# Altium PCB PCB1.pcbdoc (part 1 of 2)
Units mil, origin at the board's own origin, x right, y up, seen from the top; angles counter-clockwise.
Board outline 4437 x 2665.4 mil, 2 copper layers (Top Layer, Bottom Layer), stack 62.206 mil thick; 104 components, 74 nets, 471 pads, 378 vias.
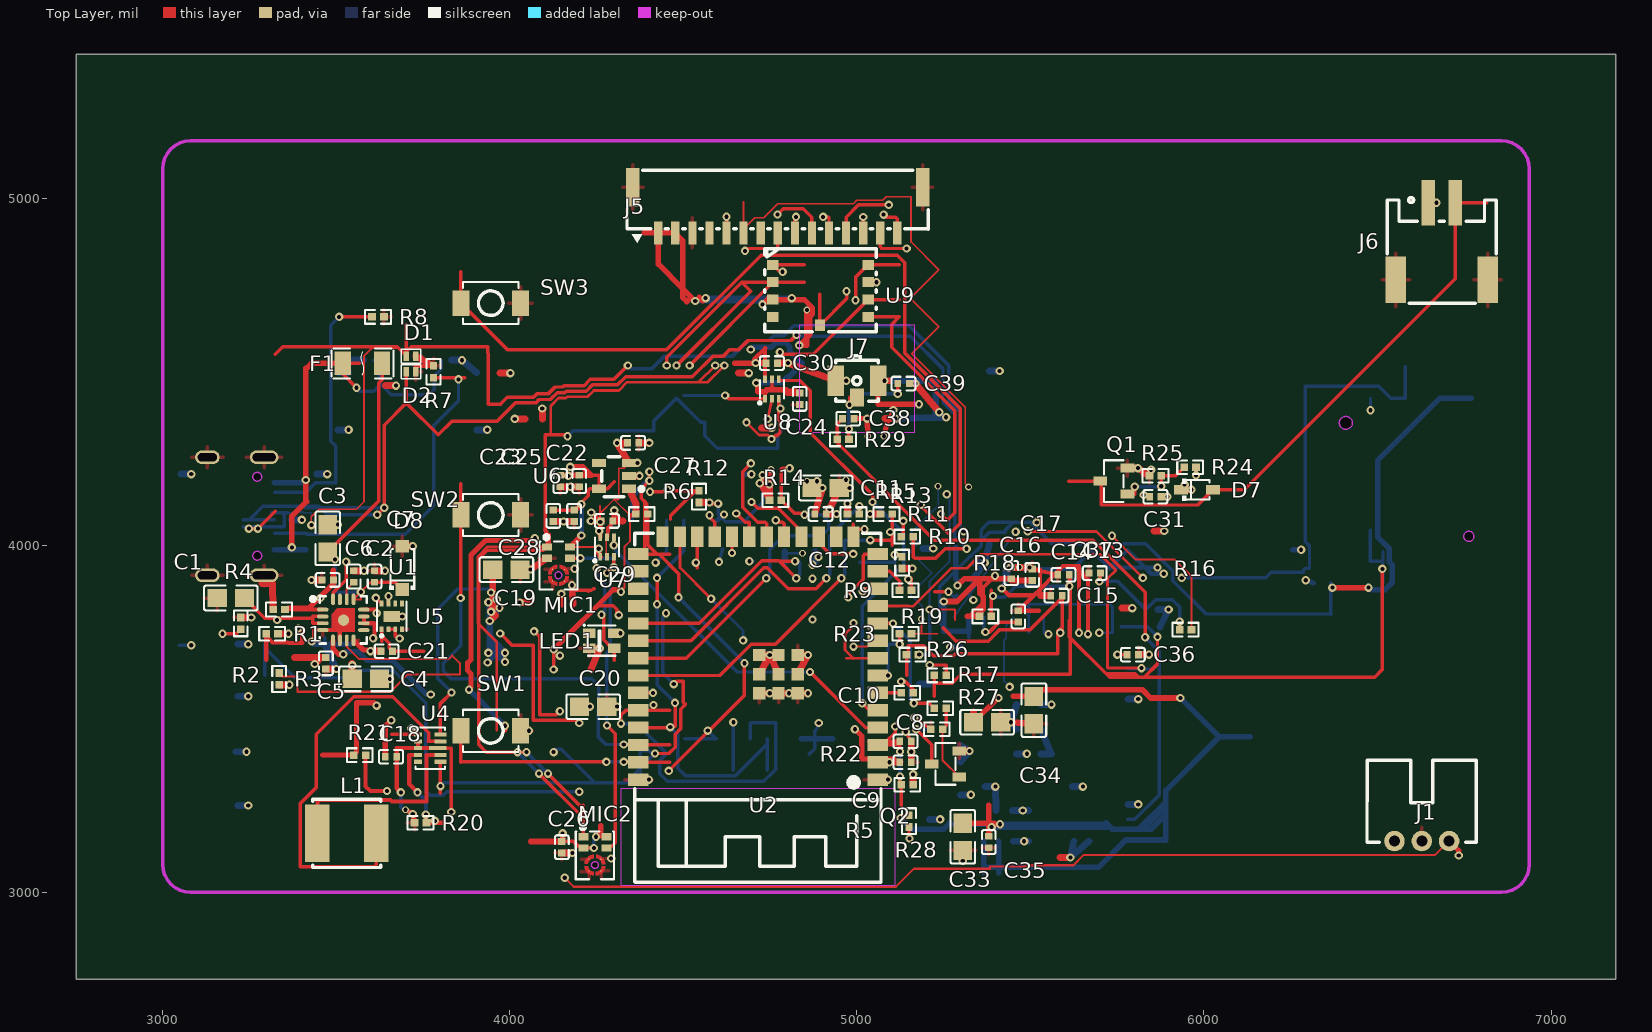
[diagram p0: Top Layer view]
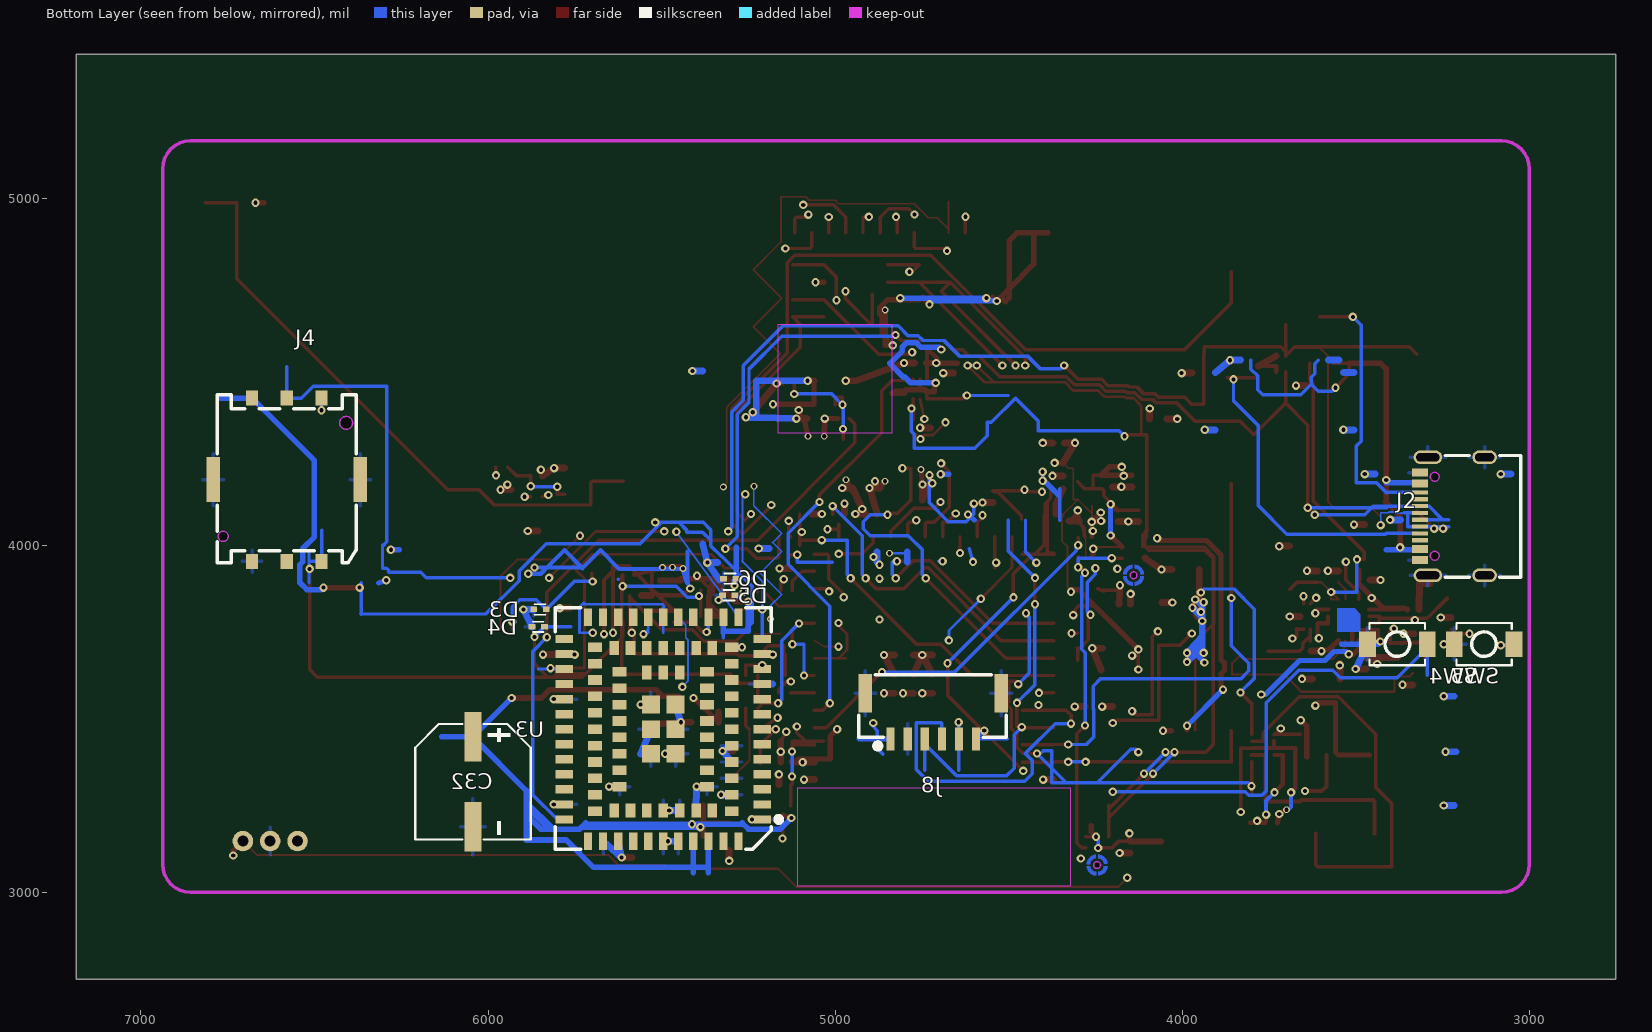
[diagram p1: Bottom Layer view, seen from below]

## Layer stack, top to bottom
Top Solder Mask Layer: solder mask 0.394, Dk 3.3
Top Layer: signal copper 1.379
Dielectric1: surface 59.449, FR4, Dk 4.5
Bottom Layer: signal copper 1.378
Bottom Solder Mask Layer: solder mask 0.394, Dk 3.3

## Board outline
7187,2750 2750,2750 2750,5415.4 7187,5415.4

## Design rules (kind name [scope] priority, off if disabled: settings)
BoardOutlineClearance copperThickness1oz [All] p0: genericclearance=10 ignorepadtopadclearanceinfootprint=FALSE except(0: Arc-SplitContinuation Track-SplitContinuation SMDPad-SplitContinuation THPad-SplitContinuation Via-SplitContinuation Fill-SplitContinuation Poly-SplitContinuation Region-SplitContinuation Text-SplitContinuation)
BoardOutlineClearance copperThickness2oz [All] p0: genericclearance=10 ignorepadtopadclearanceinfootprint=FALSE except(0: Arc-SplitContinuation Track-SplitContinuation SMDPad-SplitContinuation THPad-SplitContinuation Via-SplitContinuation Fill-SplitContinuation Poly-SplitContinuation Region-SplitContinuation Text-SplitContinuation)
BoardOutlineClearance otherClearance [All] p0: genericclearance=10 ignorepadtopadclearanceinfootprint=FALSE except(0: Arc-SplitContinuation Track-SplitContinuation SMDPad-SplitContinuation THPad-SplitContinuation Via-SplitContinuation Fill-SplitContinuation Poly-SplitContinuation Region-SplitContinuation Text-SplitContinuation)
Clearance copperThickness1oz [All] p1: gap=7 ignorepadtopadclearanceinfootprint=FALSE
Clearance copperThickness2oz [All] p1: gap=7 ignorepadtopadclearanceinfootprint=FALSE
Clearance otherClearance [All] p1: gap=7 ignorepadtopadclearanceinfootprint=FALSE
DiffPairsRouting differentialPair [All] p1: maxuncoupledlength=10 minlimit=6 maxlimit=Infinity mostfreqgap=6 toplayer_minwidth=5 toplayer_prefwidth=10 toplayer_maxwidth=100 bottomlayer_minwidth=5 bottomlayer_prefwidth=10 bottomlayer_maxwidth=100
PasteMaskExpansion pasteMaskExpansion [All] p1: expansion=0
PlaneConnect innerPlane [All] p1: planeconnectstyle=Relief reliefexpansion=20 reliefentries=4 reliefconductorwidth=10 reliefairgap=10
PolygonConnect copperRegion [All] p1: connectstyle=Relief reliefentries=4 reliefconductorwidth=10 polygonreliefangle="90 Angle" airgapwidth=10
RoutingVias viaSize [All] p1: viastyle="Through Hole" holewidth=12.0078 minholewidth=11.811 maxholewidth=248.0314 width=12.0078 minwidth=11.811 maxwidth=248.0314
SolderMaskExpansion solderMaskExpansion [IsVia] p1: useseparateexpansions=TRUE expansion=-1000 expansionbottom=-1000
SolderMaskExpansion solderMaskExpansion [All] p2: useseparateexpansions=TRUE expansion=2 expansionbottom=2
Width copperThickness1oz [All] p1: maxlimit=100 minlimit=5 preferedwidth=10
Width copperThickness2oz [All] p1: maxlimit=100 minlimit=8 preferedwidth=10

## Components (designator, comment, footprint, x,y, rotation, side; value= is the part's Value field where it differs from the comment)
C1 "10uF" C0805 3196.06,3848.03 r180 top
C2 "1uF" C0402 3610,3910 r90 top
C3 "10uF" C0805 3475,4020 r90 top
C4 "10uF" C0805 3585,3615 r0 top
C5 "100nF" C0402 3470,3660 r270 top
C6 "100nF" C0402 3550,3910 r90 top
C7 "100nF" C0402 3475,3900 r180 top
C8 "10uF" C0805 5375,3490 r0 top
C9 "100nF" C0402 5140,3375 r0 top
C10 "1uF" C0402 5140,3435 r0 top
C11 "10uF" C0805 4910,4165 r0 top
C12 "100nF" C0402 4895,4090 r0 top
C13 "33pF" C0402 5685,3920 r180 top
C14 "33pF" C0402 5595,3915 r180 top
C15 "33pF" C0402 5575,3855 r180 top
C16 "100nF" C0402 5445,3920 r90 top
C17 "33pF" C0402 5505,3915 r90 top
C18 "100nF" C0402 3657.5,3390.5 r0 top
C19 "10uF" C0805 3990,3930 r0 top
C20 "22uF" C0805 4240,3535 r0 top
C21 "100nF" C0402 3645,3695 r180 top
C22 "100nF" C0402 4145,4185 r270 top
C23 "100nF" C0402 4125,4085 r270 top
C24 "100nF" C0402 4835,4422 r270 top
C25 "100nF" C0402 4185,4085 r270 top
C26 "100nF" C0402 4150,3130 r270 top
C27 "1uF" C0402 4355,4295 r0 top
C28 "1uF" C0402 4200,4185 r270 top
C29 "100nF" C0402 4280,4070 r0 top
C30 "100nF" C0402 4755,4525 r0 top
C31 "100nF" C0402 5860,4140 r0 top
C32 "470uF" CAP-SMD_BD8.0-L8.3-W8.3-LS9.1-FD_RYRVE6.3V1000UF8X10 6043.31,3318.9 r270 bottom
C33 "22uF" C0805 5305,3160 r270 top
C34 "22uF" C0805 5510,3525 r270 top
C35 "100nF" C0402 5380,3145 r270 top
C36 "100nF" C0402 5795,3685 r0 top
C37 "10nF" C0402 5465,3795 r90 top
C38 "1pF" C0402 4975,4365 r0 top
C39 "1pF" C0402 5134,4466 r0 top
D1 "ESD5311N-2/TR" X1-DFN1006-2_L1.0-W0.6_ESD5311N-2-TR 3715,4545 r0 top locked
D2 "ESD5311N-2/TR" X1-DFN1006-2_L1.0-W0.6_ESD5311N-2-TR 3715,4500 r0 top locked
D3 "ESD9B5.0ST5G" SOD-923_L0.8-W0.6-LS1.0-BI 5850,3815 r0 bottom
D4 "ESD9B5.0ST5G" SOD-923_L0.8-W0.6-LS1.0-BI 5855,3765 r0 bottom
D5 "ESD9B5.0ST5G" SOD-923_L0.8-W0.6-LS1.0-BI 5306,3856 r0 bottom
D6 "ESD9B5.0ST5G" SOD-923_L0.8-W0.6-LS1.0-BI 5303,3904 r0 bottom
D7 "1N5819WS" SOD-323_L1.8-W1.3-LS2.5-RD 5980,4160 r0 top
D8 "SMF5.0A" SOD-123FL_L2.8-W1.7-LS3.6-RD 3690,3935 r90 top
F1 "1206L100/6NR" F1206 3575,4524 r0 top locked
J1 "PH-3AW" CONN-TH_3P-P2.00_DEALON_PH-3AW_C2904959 6627.54,3147.69 r180 top
J2 "TYPE-C16PIN" USB-C-SMD_TYPE-C16PIN 3221.5,4083.46 r90 bottom
J4 "NANO_SIM" SIM-SMD_XKB_XKNANO-1151 6579.72,4188.99 r0 bottom
J5 "BM15B-GHS-TBT" CONN-SMD_15P-P1.25_L5.0-W20.8 4771.85,4966 r180 top locked
J6 "XY-PH2.0-2PWT" CONN-SMD_XY-PH2.0-2PWT 6685.04,4875.73 r0 top
J7 "6GHz" RF-SMD_U.FL-R-SMT-1-80 5000,4450 r0 top locked
J8 "BM06B-GHS-TBT" CONN-SMD_6P-P1.25_BM06B-GHS-TBT 4716.93,3507.87 r0 bottom
L1 "1uH" IND-SMD_L5.0-W5.0_FNR50XXS 3530,3170 r180 top
LED1 "WS2812C-2020-V6/W" LED-SMD_4P-L2.0-W2.0-TL_WS2812B-2020 4265,3725 r0 top locked
MIC1 "MSM261DDB019" RHLGA-5L_L3.5-W2.7-P0.82-MSM261DDB019 4140,3945 r0 top locked
MIC2 "MSM261DDB019" RHLGA-5L_L3.5-W2.7-P0.82-MSM261DDB019 4245,3110 r0 top locked
Q1 "AO3400A" SOT-23-3_L2.9-W1.3-P1.90-LS2.4-BR 5740,4185 r0 top
Q2 "MMBT3904(RANGE:100-300)" SOT-23-3_L2.9-W1.3-P1.90-LS2.4-BR 5255,3370 r0 top
R1 "1.8kΩ" R0402 3315,3745 r0 top
R2 "1.1kΩ" R0402 3225,3775 r90 top
R3 "100kΩ" R0402 3335,3615 r270 top
R4 "10kΩ" R0402 3335,3815 r180 top
R5 "10kΩ" R0402 5145,3310 r0 top
R6 "10kΩ" R0402 4380,4090 r180 top
R7 "5.1kΩ" R0402 3780,4500 r90 top
R8 "5.1kΩ" R0402 3620,4658 r0 top
R9 "22Ω" R0402 5140,3870 r0 top
R10 "22Ω" R0402 5145,4025 r0 top
R11 "10kΩ" R0402 5085,4090 r180 top
R12 "10kΩ" R0402 4545,4140 r270 top
R13 "10kΩ" R0402 5130,3950 r270 top
R14 "10kΩ" R0402 4765,4130 r180 top
R15 "10kΩ" R0402 4990,4090 r180 top
R16 "22Ω" R0402 5946.85,3757.09 r180 top
R17 "22Ω" R0402 5240,3625 r180 top
R18 "10kΩ" R0402 5370,3795 r180 top
R19 "22Ω" R0402 5160,3685 r180 top
R20 "91kΩ" R0402 3742.5,3200.5 r180 top
R21 "511kΩ" R0402 3567.5,3395.5 r0 top
R22 "22Ω" R0402 5145,3575 r0 top
R23 "22Ω" R0402 5140,3745 r0 top
R24 "100Ω" R0402 5960,4225 r180 top
R25 "100kΩ" R0402 5860,4200 r180 top
R26 "4.7kΩ" R0402 5240,3530 r0 top
R27 "47kΩ" R0402 5230,3470 r180 top
R28 "0Ω" R0402 5150,3205 r90 top
R29 "0Ω" R0402 4960,4305 r0 top
SW1 "TS-1088-AR02016" SW-SMD_L3.9-W3.0-P4.45 3944.88,3465.35 r0 top
SW2 "TS-1088-AR02016" SW-SMD_L3.9-W3.0-P4.45 3944.88,4087.4 r0 top
SW3 "TS-1088-AR02016" SW-SMD_L3.9-W3.0-P4.45 3944.88,4697.64 r0 top
SW4 "TS-1088-AR02016" SW-SMD_L3.9-W3.0-P4.45 3380,3715 r0 bottom locked
SW5 "TS-1088-AR02016" SW-SMD_L3.9-W3.0-P4.45 3130,3715 r0 bottom locked
U1 "BQ24074RGTR" QFN-16_L3.0-W3.0-P0.50-TL-EP1.7 3520,3785 r0 top locked
U2 "2.4GHz" WIRELM-SMD_ESP32-S3-WROOM-1 4715,3675 r180 top locked
U3 "AIR780E" LGA-109_L17.7-W15.8-AIR780E 5495,3470 r0 bottom locked
U4 "TPS63802DLAR" VSON-10_L3.0-W2.0-P0.50-TL 3767.5,3415.5 r0 top
U5 "MAX17048G+T10" TDFN-8_L2.0-W2.0-P0.50-BL-EP1.2 3660,3795 r0 top locked
U6 "TLV75518PDBVR" SOT-23-5_L2.9-W1.6-P0.95-LS2.8-BR 4300,4200 r0 top locked
U7 "SN74AXC1T45DRLR" SOT-563_L1.6-W1.2-P0.50-LS1.6-BL 4280,3995 r0 top locked
U8 "SN74AXC1T45DRLR" SOT-563_L1.6-W1.2-P0.50-LS1.6-BL 4755,4450 r0 top locked
U9 "CSNP4GCR01-BPW" LGA-8_L8.0-W6.0-P1.27 4894.99,4720.83 r0 top

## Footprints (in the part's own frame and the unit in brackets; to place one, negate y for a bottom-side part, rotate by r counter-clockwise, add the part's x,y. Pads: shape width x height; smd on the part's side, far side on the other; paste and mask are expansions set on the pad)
C0402 [mm]
  rect 0.5x0.54 smd: 1(-0.42,0) 2(0.42,0)
  silkscreen extent -0.87,-0.5 0.87,0.5
C0805 [mm]
  rect 1.41x1.35 smd paste-100 mask+0.051: 1(-1,0) 2(1,0)
  silkscreen extent -1.96,-0.9 1.96,0.9
CAP-SMD_BD8.0-L8.3-W8.3-LS9.1-FD_RYRVE6.3V1000UF8X10 [mm]
  rect 3.61x1.26 smd: 1(-3.295,0) 2(3.295,0)
  silkscreen extent -4.23,-4.23 4.23,4.23
CONN-SMD_6P-P1.25_BM06B-GHS-TBT [mm]
  rect 0.6x1.7 smd: 1(3.125,1.675) 2(1.875,1.675) 3(0.625,1.675) 4(-0.625,1.675) 5(-1.875,1.675) 6(-3.125,1.675)
  rect 1x2.8 smd: 7(-4.975,-1.675) 8(4.975,-1.675)
  silkscreen extent -5.33,-3.02 5.46,2.59
CONN-SMD_15P-P1.25_L5.0-W20.8 [mm]
  rect 0.6x1.7 smd: 1(8.749,1.675) 2(7.499,1.675) 3(6.248,1.675) 4(4.998,1.675) 5(3.749,1.675) 6(2.499,1.675) 7(1.248,1.675) 8(-0.001,1.675) 9(-1.251,1.675) 10(-2.501,1.675) 11(-3.752,1.675) 12(-5.001,1.675) 13(-6.251,1.675) 14(-7.502,1.675) 15(-8.752,1.675)
  rect 1x2.8 smd: 16(-10.6,-1.675) 17(10.6,-1.675)
  silkscreen extent -11.02,-2.9 11.03,2.41
CONN-SMD_XY-PH2.0-2PWT [mm]
  rect 1x3.3 smd: 1(-1,2.825) 2(1,2.825)
  rect 1.5x3.4 smd: 3(3.35,-2.825) 4(-3.35,-2.825)
  silkscreen extent -3.98,-4.53 3.97,3.2
CONN-TH_3P-P2.00_DEALON_PH-3AW_C2904959 [mm]
  round 1.5 hole 0.8: 1(2,0) 2(0,0) 3(-2,0)
  silkscreen extent -4,-5.9 4.01,0.1
F1206 [mm]
  rect 1.19x1.728 smd: 1(-1.445,0) 2(1.445,0)
  silkscreen extent -2.27,-1.09 2.27,1.09
IND-SMD_L5.0-W5.0_FNR50XXS [mm]
  rect 1.8x4.2 smd: 1(-2.15,0) 2(2.15,0)
  silkscreen extent -2.5,-2.5 2.5,2.5
LED-SMD_4P-L2.0-W2.0-TL_WS2812B-2020 [mm]
  rect 0.9x0.7 smd: 1(-0.915,0.55) 2(-0.915,-0.55) 3(0.915,-0.55) 4(0.915,0.55)
  silkscreen extent -1.3,-1.1 1,1.15
LGA-8_L8.0-W6.0-P1.27 [mm]
  rect 0.74x0.85 smd paste+0 mask+0.05: 1(-0.047,-2.215)
  rect 0.85x0.74 smd paste+0 mask+0.05: 2(3.49,-1.595) 3(3.49,-0.325) 4(3.49,0.945) 5(3.49,2.215) 6(-3.49,2.215) 7(-3.49,0.945) 8(-3.49,-0.325) 9(-3.49,-1.595)
  silkscreen extent -4.06,-2.69 4.06,3.41
LGA-109_L17.7-W15.8-AIR780E [mm]
  rect 1.3x0.6 smd paste+0 mask+0.05: 1(-7.25,6.6) 2(-7.25,5.5) 3(-7.25,4.4) 4(-7.25,3.3) 5(-7.25,2.2) 6(-7.25,1.1) 7(-7.25,0) 8(-7.25,-1.1) 9(-7.25,-2.2) 10(-7.25,-3.3) 11(-7.25,-4.4) 12(-7.25,-5.5) 13(-7.25,-6.6) 23(7.25,-6.6) 24(7.25,-5.5) 25(7.25,-4.4) 26(7.25,-3.3) 27(7.25,-2.2) 28(7.25,-1.1) 29(7.25,0) 30(7.25,1.1) 31(7.25,2.2) 32(7.25,3.3) 33(7.25,4.4) 34(7.25,5.5) 35(7.25,6.6)
  rect 0.6x1.3 smd paste+0 mask+0.05: 14(-4.4,-8.2) 15(-3.3,-8.2) 16(-2.2,-8.2) 17(-1.1,-8.2) 18(0,-8.2) 19(1.1,-8.2) 20(2.2,-8.2) 21(3.3,-8.2) 22(4.4,-8.2) 36(4.4,8.2) 37(3.3,8.2) 38(2.2,8.2) 39(1.1,8.2) 40(0,8.2) 41(-1.1,8.2) 42(-2.2,8.2) 43(-3.3,8.2) 44(-4.4,8.2) 95(-5.5,-8.2) 96(5.5,-8.2) 97(5.5,8.2) 98(-5.5,8.2)
  rect 1x0.7 smd paste+0 mask+0.05: 45(-5,4.8) 46(-5,3.6) 47(-5,2.4) 48(-5,1.2) 49(-5,0) 50(-5,-1.2) 51(-5,-2.4) 52(-5,-3.6) 53(-5,-4.8) 59(5,-4.8) 60(5,-3.6) 61(5,-2.4) 62(5,-1.2) 63(5,0) 64(5,1.2) 65(5,2.4) 66(5,3.6) 67(5,4.8) 73(-3.2,4.2) 74(-3.2,3) 75(-3.2,1.8) 76(-3.2,0.6) 77(-3.2,-0.6) 78(-3.2,-1.8) 79(-3.2,-3) 80(-3.2,-4.2) 81(3.2,-4.2) 82(3.2,-3) 83(3.2,-1.8) 84(3.2,-0.6) 85(3.2,0.6) 86(3.2,1.8) 87(3.2,3) 88(3.2,4.2) 99(-5,6) 100(-5,-6) 103(5,-6) 104(5,6)
  rect 0.7x1 smd paste+0 mask+0.05: 54(-2.4,-5.95) 55(-1.2,-5.95) 56(0,-5.95) 57(1.2,-5.95) 58(2.4,-5.95) 68(2.4,5.95) 69(1.2,5.95) 70(0,5.95) 71(-1.2,5.95) 72(-2.4,5.95) 101(-3.6,-5.95) 102(3.6,-5.95) 105(3.6,5.95) 106(-3.6,5.95) 107(-1.2,-4.15) 108(0,-4.15) 109(1.2,-4.15)
  rect 1.3x1.3 smd paste+0 mask+0.05: 89(-0.9,1.8) 90(-0.9,0) 91(-0.9,-1.8) 92(0.9,-1.8) 93(0.9,0) 94(0.9,1.8)
  silkscreen extent -8.65,-8.9 7.9,8.8
QFN-16_L3.0-W3.0-P0.50-TL-EP1.7 [mm]
  oval 0.85x0.28 smd paste-100 mask+0.05: 1(-1.5,0.75) 2(-1.5,0.25) 3(-1.5,-0.25) 4(-1.5,-0.75) 9(1.5,-0.75) 10(1.5,-0.25) 11(1.5,0.25) 12(1.5,0.75)
  oval 0.28x0.85 smd paste-100 mask+0.05: 5(-0.75,-1.5) 6(-0.25,-1.5) 7(0.25,-1.5) 8(0.75,-1.5) 13(0.75,1.5) 14(0.25,1.5) 15(-0.25,1.5) 16(-0.75,1.5)
  round 0.827 smd: 17(0.023,-0.023)
  Top Layer region: 0.85,0.85 0.85,-0.85 -0.85,-0.85 -0.85,0.425 -0.425,0.85
  Bottom Layer region: 0.85,0.85 0.85,-0.85 -0.85,-0.85 -0.85,0.425 -0.425,0.85
  Multi-Layer region: 0.85,0.85 0.85,-0.85 -0.85,-0.85 -0.85,0.425 -0.425,0.85
  silkscreen extent -2.38,-1.72 1.72,1.73
R0402 [mm]
  rect 0.566x0.54 smd paste-100 mask+0.051: 1(-0.433,0) 2(0.433,0)
  silkscreen extent -0.94,-0.5 0.94,0.5
RF-SMD_U.FL-R-SMT-1-80 [mm]
  rect 1.2x2.2 smd: 1(-1.55,0.612) 3(1.55,0.612)
  rect 1x1.3 smd: 2(0,-0.612)
  silkscreen extent -1.55,-0.89 1.55,2.43
RHLGA-5L_L3.5-W2.7-P0.82-MSM261DDB019 [mm]
  rect 0.73x0.53 smd paste+0 mask+0.05: 1(-0.838,1.276) 2(-0.838,0.455) 4(0.838,0.455) 5(0.838,1.276)
  round 0.086 smd: 3(-0.437,-1.224) 3(-0.426,-0.36) 3(0.426,-1.235) 3(0.437,-0.371)
  Top Layer region: 0.085,-0.29 0.084,-0.039 0.144,-0.045 0.202,-0.055 0.265,-0.072 0.335,-0.099 0.382,-0.122 0.418,-0.143 0.453,-0.165 0.483,-0.187 0.513,-0.212 0.551,-0.247 0.588,-0.286 0.627,-0.335 0.659,-0.383 0.685,-0.429 0.703,-0.466 0.728,-0.533 0.745,-0.593 0.758,-0.662 0.764,-0.725 0.506,-0.725 0.503,-0.695 0.491,-0.634 0.478,-0.595 0.465,-0.56 0.43,-0.499 0.404,-0.462 0.373,-0.428 0.318,-0.381 0.247,-0.333 0.172,-0.306
  Top Layer region: -0.508,-0.712 -0.759,-0.713 -0.753,-0.653 -0.743,-0.595 -0.726,-0.532 -0.699,-0.462 -0.676,-0.415 -0.655,-0.379 -0.633,-0.344 -0.611,-0.314 -0.586,-0.284 -0.551,-0.246 -0.512,-0.209 -0.463,-0.17 -0.415,-0.138 -0.369,-0.112 -0.332,-0.094 -0.265,-0.069 -0.205,-0.052 -0.136,-0.039 -0.073,-0.033 -0.073,-0.291 -0.103,-0.294 -0.164,-0.306 -0.203,-0.319 -0.238,-0.332 -0.299,-0.367 -0.336,-0.393 -0.37,-0.424 -0.417,-0.479 -0.465,-0.55 -0.492,-0.625
  Top Layer region: -0.085,-1.305 -0.084,-1.556 -0.144,-1.55 -0.202,-1.54 -0.265,-1.523 -0.335,-1.496 -0.382,-1.473 -0.418,-1.452 -0.453,-1.43 -0.483,-1.408 -0.513,-1.383 -0.551,-1.348 -0.588,-1.309 -0.627,-1.26 -0.659,-1.212 -0.685,-1.166 -0.703,-1.129 -0.728,-1.062 -0.745,-1.002 -0.758,-0.933 -0.764,-0.87 -0.506,-0.87 -0.503,-0.9 -0.491,-0.961 -0.478,-1 -0.465,-1.035 -0.43,-1.096 -0.404,-1.133 -0.373,-1.167 -0.318,-1.214 -0.247,-1.262 -0.172,-1.289
  Top Layer region: 0.508,-0.882 0.759,-0.881 0.753,-0.941 0.743,-0.999 0.726,-1.062 0.699,-1.132 0.676,-1.179 0.655,-1.215 0.633,-1.25 0.611,-1.28 0.586,-1.31 0.551,-1.348 0.512,-1.385 0.463,-1.424 0.415,-1.456 0.369,-1.482 0.332,-1.5 0.265,-1.525 0.205,-1.542 0.136,-1.555 0.073,-1.561 0.073,-1.303 0.103,-1.3 0.164,-1.288 0.203,-1.275 0.238,-1.262 0.299,-1.227 0.336,-1.201 0.37,-1.17 0.417,-1.115 0.465,-1.044 0.492,-0.969
  Bottom Layer region: 0.085,-0.29 0.084,-0.039 0.144,-0.045 0.202,-0.055 0.265,-0.072 0.335,-0.099 0.382,-0.122 0.418,-0.143 0.453,-0.165 0.483,-0.187 0.513,-0.212 0.551,-0.247 0.588,-0.286 0.627,-0.335 0.659,-0.383 0.685,-0.429 0.703,-0.466 0.728,-0.533 0.745,-0.593 0.758,-0.662 0.764,-0.725 0.506,-0.725 0.503,-0.695 0.491,-0.634 0.478,-0.595 0.465,-0.56 0.43,-0.499 0.404,-0.462 0.373,-0.428 0.318,-0.381 0.247,-0.333 0.172,-0.306
  Bottom Layer region: -0.508,-0.712 -0.759,-0.713 -0.753,-0.653 -0.743,-0.595 -0.726,-0.532 -0.699,-0.462 -0.676,-0.415 -0.655,-0.379 -0.633,-0.344 -0.611,-0.314 -0.586,-0.284 -0.551,-0.246 -0.512,-0.209 -0.463,-0.17 -0.415,-0.138 -0.369,-0.112 -0.332,-0.094 -0.265,-0.069 -0.205,-0.052 -0.136,-0.039 -0.073,-0.033 -0.073,-0.291 -0.103,-0.294 -0.164,-0.306 -0.203,-0.319 -0.238,-0.332 -0.299,-0.367 -0.336,-0.393 -0.37,-0.424 -0.417,-0.479 -0.465,-0.55 -0.492,-0.625
  Bottom Layer region: -0.085,-1.305 -0.084,-1.556 -0.144,-1.55 -0.202,-1.54 -0.265,-1.523 -0.335,-1.496 -0.382,-1.473 -0.418,-1.452 -0.453,-1.43 -0.483,-1.408 -0.513,-1.383 -0.551,-1.348 -0.588,-1.309 -0.627,-1.26 -0.659,-1.212 -0.685,-1.166 -0.703,-1.129 -0.728,-1.062 -0.745,-1.002 -0.758,-0.933 -0.764,-0.87 -0.506,-0.87 -0.503,-0.9 -0.491,-0.961 -0.478,-1 -0.465,-1.035 -0.43,-1.096 -0.404,-1.133 -0.373,-1.167 -0.318,-1.214 -0.247,-1.262 -0.172,-1.289
  Bottom Layer region: 0.508,-0.882 0.759,-0.881 0.753,-0.941 0.743,-0.999 0.726,-1.062 0.699,-1.132 0.676,-1.179 0.655,-1.215 0.633,-1.25 0.611,-1.28 0.586,-1.31 0.551,-1.348 0.512,-1.385 0.463,-1.424 0.415,-1.456 0.369,-1.482 0.332,-1.5 0.265,-1.525 0.205,-1.542 0.136,-1.555 0.073,-1.561 0.073,-1.303 0.103,-1.3 0.164,-1.288 0.203,-1.275 0.238,-1.262 0.299,-1.227 0.336,-1.201 0.37,-1.17 0.417,-1.115 0.465,-1.044 0.492,-0.969
  Board Outline Layer circle w0.003: c0,-0.797 r0.25
  Board Outline Layer region: 0.25,-0.797 0.225,-0.906 0.156,-0.993 0.056,-1.041 -0.056,-1.041 -0.156,-0.993 -0.225,-0.906 -0.25,-0.797 -0.25,-0.797 -0.225,-0.689 -0.156,-0.602 -0.056,-0.554 0.056,-0.554 0.156,-0.602 0.225,-0.689 0.25,-0.797
  Board Outline Layer region: 0.25,-0.797 0.241,-0.862 0.217,-0.922 0.177,-0.974 0.125,-1.014 0.065,-1.039 0,-1.047 -0.065,-1.039 -0.125,-1.014 -0.177,-0.974 -0.217,-0.922 -0.241,-0.862 -0.25,-0.797 -0.241,-0.733 -0.217,-0.672 -0.177,-0.621 -0.125,-0.581 -0.065,-0.556 0,-0.547 0.065,-0.556 0.125,-0.581 0.177,-0.621 0.217,-0.672 0.241,-0.733
  Multi-Layer region: 0.085,-0.29 0.084,-0.039 0.144,-0.045 0.202,-0.055 0.265,-0.072 0.335,-0.099 0.382,-0.122 0.418,-0.143 0.453,-0.165 0.483,-0.187 0.513,-0.212 0.551,-0.247 0.588,-0.286 0.627,-0.335 0.659,-0.383 0.685,-0.429 0.703,-0.466 0.728,-0.533 0.745,-0.593 0.758,-0.662 0.764,-0.725 0.506,-0.725 0.503,-0.695 0.491,-0.634 0.478,-0.595 0.465,-0.56 0.43,-0.499 0.404,-0.462 0.373,-0.428 0.318,-0.381 0.247,-0.333 0.172,-0.306
  Multi-Layer region: -0.508,-0.712 -0.759,-0.713 -0.753,-0.653 -0.743,-0.595 -0.726,-0.532 -0.699,-0.462 -0.676,-0.415 -0.655,-0.379 -0.633,-0.344 -0.611,-0.314 -0.586,-0.284 -0.551,-0.246 -0.512,-0.209 -0.463,-0.17 -0.415,-0.138 -0.369,-0.112 -0.332,-0.094 -0.265,-0.069 -0.205,-0.052 -0.136,-0.039 -0.073,-0.033 -0.073,-0.291 -0.103,-0.294 -0.164,-0.306 -0.203,-0.319 -0.238,-0.332 -0.299,-0.367 -0.336,-0.393 -0.37,-0.424 -0.417,-0.479 -0.465,-0.55 -0.492,-0.625
  Multi-Layer region: -0.085,-1.305 -0.084,-1.556 -0.144,-1.55 -0.202,-1.54 -0.265,-1.523 -0.335,-1.496 -0.382,-1.473 -0.418,-1.452 -0.453,-1.43 -0.483,-1.408 -0.513,-1.383 -0.551,-1.348 -0.588,-1.309 -0.627,-1.26 -0.659,-1.212 -0.685,-1.166 -0.703,-1.129 -0.728,-1.062 -0.745,-1.002 -0.758,-0.933 -0.764,-0.87 -0.506,-0.87 -0.503,-0.9 -0.491,-0.961 -0.478,-1 -0.465,-1.035 -0.43,-1.096 -0.404,-1.133 -0.373,-1.167 -0.318,-1.214 -0.247,-1.262 -0.172,-1.289
  Multi-Layer region: 0.508,-0.882 0.759,-0.881 0.753,-0.941 0.743,-0.999 0.726,-1.062 0.699,-1.132 0.676,-1.179 0.655,-1.215 0.633,-1.25 0.611,-1.28 0.586,-1.31 0.551,-1.348 0.512,-1.385 0.463,-1.424 0.415,-1.456 0.369,-1.482 0.332,-1.5 0.265,-1.525 0.205,-1.542 0.136,-1.555 0.073,-1.561 0.073,-1.303 0.103,-1.3 0.164,-1.288 0.203,-1.275 0.238,-1.262 0.299,-1.227 0.336,-1.201 0.37,-1.17 0.417,-1.115 0.465,-1.044 0.492,-0.969
  Multi-Layer board cut-out: 0.25,-0.797 0.225,-0.906 0.156,-0.993 0.056,-1.041 -0.056,-1.041 -0.156,-0.993 -0.225,-0.906 -0.25,-0.797 -0.25,-0.797 -0.225,-0.689 -0.156,-0.602 -0.056,-0.554 0.056,-0.554 0.156,-0.602 0.225,-0.689 0.25,-0.797
  silkscreen extent -1.4,-1.84 1.4,2.13
SIM-SMD_XKB_XKNANO-1151 [mm]
  rect 1x3.29 smd paste+0 mask+0.05: 8(-5.385,-0.005) 8(5.385,-0.005)
  rect 0.9x1.1 smd paste+0 mask+0.05: C1(2.54,-5.975) C2(0,-5.975) C3(-2.54,-5.975) C5(2.54,5.975) C6(0,5.975) C7(-2.54,5.975)
  Board Outline Layer circle w0.003: c4.66,4.145 r0.375
  Board Outline Layer circle w0.003: c-4.34,-4.155 r0.475
  Board Outline Layer region: 5.035,4.145 4.998,4.308 4.894,4.438 4.744,4.511 4.577,4.511 4.426,4.438 4.322,4.308 4.285,4.145 4.285,4.145 4.322,3.982 4.426,3.852 4.577,3.779 4.744,3.779 4.894,3.852 4.998,3.982 5.035,4.145
  Board Outline Layer region: 5.035,4.145 5.026,4.228 4.998,4.308 4.953,4.379 4.894,4.438 4.823,4.483 4.744,4.511 4.66,4.52 4.577,4.511 4.497,4.483 4.426,4.438 4.367,4.379 4.322,4.308 4.295,4.228 4.285,4.145 4.295,4.061 4.322,3.982 4.367,3.911 4.426,3.852 4.497,3.807 4.577,3.779 4.66,3.77 4.744,3.779 4.823,3.807 4.894,3.852 4.953,3.911 4.998,3.982 5.026,4.061
  Board Outline Layer region: -3.865,-4.155 -3.912,-3.949 -4.044,-3.784 -4.234,-3.692 -4.446,-3.692 -4.636,-3.784 -4.768,-3.949 -4.815,-4.155 -4.815,-4.155 -4.768,-4.361 -4.636,-4.526 -4.446,-4.618 -4.234,-4.618 -4.044,-4.526 -3.912,-4.361 -3.865,-4.155
  Board Outline Layer region: -3.865,-4.155 -3.874,-4.062 -3.901,-3.973 -3.945,-3.891 -4.004,-3.819 -4.076,-3.76 -4.158,-3.716 -4.247,-3.689 -4.34,-3.68 -4.433,-3.689 -4.522,-3.716 -4.604,-3.76 -4.676,-3.819 -4.735,-3.891 -4.779,-3.973 -4.806,-4.062 -4.815,-4.155 -4.806,-4.248 -4.779,-4.337 -4.735,-4.419 -4.676,-4.491 -4.604,-4.55 -4.522,-4.594 -4.433,-4.621 -4.34,-4.63 -4.247,-4.621 -4.158,-4.594 -4.076,-4.55 -4.004,-4.491 -3.945,-4.419 -3.901,-4.337 -3.874,-4.248
  Multi-Layer board cut-out: 5.035,4.145 4.998,4.308 4.894,4.438 4.744,4.511 4.577,4.511 4.426,4.438 4.322,4.308 4.285,4.145 4.285,4.145 4.322,3.982 4.426,3.852 4.577,3.779 4.744,3.779 4.894,3.852 4.998,3.982 5.035,4.145
  Multi-Layer board cut-out: -3.865,-4.155 -3.912,-3.949 -4.044,-3.784 -4.234,-3.692 -4.446,-3.692 -4.636,-3.784 -4.768,-3.949 -4.815,-4.155 -4.815,-4.155 -4.768,-4.361 -4.636,-4.526 -4.446,-4.618 -4.234,-4.618 -4.044,-4.526 -3.912,-4.361 -3.865,-4.155
  silkscreen extent -5.08,-6.22 5.08,6.1
SOD-123FL_L2.8-W1.7-LS3.6-RD [mm]
  rect 0.93x0.96 smd paste+0 mask+0.051: 1(-1.585,0) 2(1.585,0)
  silkscreen extent -1.6,-0.95 1.38,0.95
SOD-323_L1.8-W1.3-LS2.5-RD [mm]
  rect 1x0.7 smd: 1(-1.172,0) 2(1.172,0)
  silkscreen extent -1.08,-0.8 0.9,0.8
SOD-923_L0.8-W0.6-LS1.0-BI [mm]
  rect 0.5x0.4 smd: 1(-0.457,0) 2(0.457,0)
  silkscreen extent -0.41,-0.38 0.41,0.38
SOT-23-3_L2.9-W1.3-P1.90-LS2.4-BR [mm]
  rect 1x0.65 smd: 1(1,-0.95) 2(1,0.95) 3(-1,0)
  silkscreen extent -0.73,-1.53 0.73,1.53
SOT-23-5_L2.9-W1.6-P0.95-LS2.8-BR [mm]
  rect 1x0.6 smd paste+0 mask+0.05: 1(1.1,-0.95) 2(1.1,0) 3(1.1,0.95) 4(-1.1,0.95) 5(-1.1,-0.95)
  silkscreen extent -0.89,-1.52 2.16,1.4
SOT-563_L1.6-W1.2-P0.50-LS1.6-BL [mm]
  rect 0.28x0.545 smd: 1(-0.5,-0.723) 2(0,-0.723) 3(0.5,-0.723) 4(0.5,0.723) 5(0,0.723) 6(-0.5,0.723)
  silkscreen extent -0.99,-1.12 0.88,0.68
SW-SMD_L3.9-W3.0-P4.45 [mm]
  rect 1.23x1.86 smd: 1(-2.185,0) 2(2.185,0)
  silkscreen extent -2.03,-1.54 2.03,1.54
TDFN-8_L2.0-W2.0-P0.50-BL-EP1.2 [mm]
  rect 0.28x0.425 smd: 1(-0.75,-0.938) 2(-0.25,-0.938) 3(0.25,-0.938) 4(0.75,-0.938) 5(0.75,0.938) 6(0.25,0.938) 7(-0.25,0.938) 8(-0.75,0.938)
  rect 1.2x0.8 smd: 9(0,0)
  silkscreen extent -1.08,-1.53 1.08,1.08
USB-C-SMD_TYPE-C16PIN [mm]
  oval 1x2.1 hole 0.6 slot 1.7 at 90 deg: 1(-4.32,1.787) 2(4.32,1.787)
  oval 1x1.8 hole 0.6 slot 1.4 at 90 deg: 3(-4.32,-2.362) 4(4.32,-2.362)
  rect 0.6x1.15 smd paste-100 mask+0.051: A1B12(-3.2,2.362) A4B9(-2.4,2.362) B1A12(3.2,2.362) B4A9(2.4,2.362)
  rect 0.3x1.15 smd paste-100 mask+0.051: A5(-1.25,2.362) A6(-0.25,2.362) A7(0.25,2.362) A8(1.25,2.362) B5(1.75,2.362) B6(0.75,2.362) B7(-0.75,2.362) B8(-1.75,2.362)
  Board Outline Layer circle w0.003: c2.89,1.288 r0.325
  Board Outline Layer circle w0.003: c-2.89,1.288 r0.325
  Board Outline Layer region: 2.89,1.613 2.749,1.581 2.636,1.491 2.573,1.36 2.573,1.216 2.636,1.085 2.749,0.995 2.89,0.963 2.89,0.963 3.031,0.995 3.144,1.085 3.207,1.216 3.207,1.36 3.144,1.491 3.031,1.581 2.89,1.613
  Board Outline Layer region: 2.89,1.613 2.812,1.604 2.739,1.576 2.675,1.531 2.623,1.473 2.586,1.403 2.567,1.327 2.567,1.249 2.586,1.173 2.623,1.103 2.675,1.045 2.739,1 2.812,0.972 2.89,0.963 2.968,0.972 3.041,1 3.106,1.045 3.157,1.103 3.194,1.173 3.213,1.249 3.213,1.327 3.194,1.403 3.157,1.473 3.106,1.531 3.041,1.576 2.968,1.604
  Board Outline Layer region: -2.89,1.613 -3.031,1.581 -3.144,1.491 -3.207,1.36 -3.207,1.216 -3.144,1.085 -3.031,0.995 -2.89,0.963 -2.89,0.963 -2.749,0.995 -2.636,1.085 -2.573,1.216 -2.573,1.36 -2.636,1.491 -2.749,1.581 -2.89,1.613
  Board Outline Layer region: -2.89,1.613 -2.968,1.604 -3.041,1.576 -3.106,1.531 -3.157,1.473 -3.194,1.403 -3.213,1.327 -3.213,1.249 -3.194,1.173 -3.157,1.103 -3.106,1.045 -3.041,1 -2.968,0.972 -2.89,0.963 -2.812,0.972 -2.739,1 -2.675,1.045 -2.623,1.103 -2.586,1.173 -2.567,1.249 -2.567,1.327 -2.586,1.403 -2.623,1.473 -2.675,1.531 -2.739,1.576 -2.812,1.604
  Multi-Layer board cut-out: 2.89,1.613 2.749,1.581 2.636,1.491 2.573,1.36 2.573,1.216 2.636,1.085 2.749,0.995 2.89,0.963 2.89,0.963 3.031,0.995 3.144,1.085 3.207,1.216 3.207,1.36 3.144,1.491 3.031,1.581 2.89,1.613
  Multi-Layer board cut-out: -2.89,1.613 -3.031,1.581 -3.144,1.491 -3.207,1.36 -3.207,1.216 -3.144,1.085 -3.031,0.995 -2.89,0.963 -2.89,0.963 -2.749,0.995 -2.636,1.085 -2.573,1.216 -2.573,1.36 -2.636,1.491 -2.749,1.581 -2.89,1.613
  silkscreen extent -4.45,-5 4.45,0.52
VSON-10_L3.0-W2.0-P0.50-TL [mm]
  rect 0.6x0.3 smd: 1(-0.825,1) 2(-0.825,0.5) 3(-0.825,0) 4(-0.825,-0.5) 5(-0.825,-1)
  rect 0.9x0.3 smd: 6(0.825,-1) 7(0.825,-0.5) 9(0.825,0.5) 10(0.825,1)
  rect 1.3x0.3 smd: 8(0.625,0)
  silkscreen extent -1.42,-1.52 1.14,1.62
WIRELM-SMD_ESP32-S3-WROOM-1 [mm]
  rect 1.5x0.9 smd paste+0 mask+0.05: 1(-8.75,8.895) 2(-8.75,7.625) 3(-8.75,6.355) 4(-8.75,5.085) 5(-8.75,3.815) 6(-8.75,2.545) 7(-8.75,1.275) 8(-8.75,0.005) 9(-8.75,-1.265) 10(-8.75,-2.535) 11(-8.75,-3.805) 12(-8.75,-5.075) 13(-8.75,-6.345) 14(-8.75,-7.615) 27(8.75,-7.615) 28(8.75,-6.345) 29(8.75,-5.075) 30(8.75,-3.805) 31(8.75,-2.535) 32(8.75,-1.265) 33(8.75,0.005) 34(8.75,1.275) 35(8.75,2.545) 36(8.75,3.815) 37(8.75,5.085) 38(8.75,6.355) 39(8.75,7.625) 40(8.75,8.895)
  rect 0.9x1.5 smd paste+0 mask+0.05: 15(-6.985,-8.895) 16(-5.715,-8.895) 17(-4.445,-8.895) 18(-3.175,-8.895) 19(-1.905,-8.895) 20(-0.635,-8.895) 21(0.635,-8.895) 22(1.905,-8.895) 23(3.175,-8.895) 24(4.445,-8.895) 25(5.715,-8.895) 26(6.985,-8.865)
  rect 0.9x0.9 smd: 41(-2.9,2.575) 41(-2.9,-0.225) 41(-2.9,1.175) 41(-1.5,2.575) 41(-1.5,1.175) 41(-1.5,-0.225) 41(-0.1,2.575) 41(-0.1,1.175) 41(-0.1,-0.225)
  silkscreen extent -9,-9.14 9.02,16.39
X1-DFN1006-2_L1.0-W0.6_ESD5311N-2-TR [mm]
  rect 0.4x0.7 smd: 1(-0.35,0) 2(0.35,0)
  silkscreen extent -0.71,-0.51 0.71,0.51

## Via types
v1: diameter 24, hole 12, Top Layer to Bottom Layer, 334 vias
v2: diameter 24.02, hole 12, Top Layer to Bottom Layer, 30 vias
v3: diameter 19.8, hole 11.8, Top Layer to Bottom Layer, 8 vias
v4: diameter 19.7, hole 11.8, Top Layer to Bottom Layer, 3 vias
v5: diameter 20, hole 12, Top Layer to Bottom Layer, 3 vias

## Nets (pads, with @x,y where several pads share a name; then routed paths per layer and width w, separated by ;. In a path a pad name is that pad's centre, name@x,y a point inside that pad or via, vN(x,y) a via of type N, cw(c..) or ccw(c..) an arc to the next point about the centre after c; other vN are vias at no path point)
+1V8: C22.1 C23.1 C24.1 C25.1 C26.1 C28.1 MIC1.5 MIC2.2 MIC2.5 U6.5 U7.1 U8.1 U8.5 | length 4741.1
  Top Layer w6: MIC1.5@4172.99,3995.26 4260.3,3995.3 U7.1@4260.31,3966.55
  Top Layer w9.84: C23.1@4125,4101.54 C25.1@4185,4101.54 ; C25.1@4185,4101.54 4225.58,4142.12 4225.58,4158.01 4230.16,4162.59 U6.5@4256.69,4162.6 4256.7,4201.5 4235,4201.5 ; MIC2.2@4212.01,3127.89 v1(4242,3127.9) ; v1(4248,3160.3) 4248.3,3160.3 MIC2.5@4277.99,3160.26
  Top Layer w9.92: U6.5@4256.69,4162.6 4281.33,4162.6 4301.33,4182.6 ; v1(4620.29,4431.56) 4630.29,4421.56 U8.1@4735.31,4421.56 4735.32,4437.25 4746.07,4448 4755.32,4457.25 ; U8.5@4754.99,4478.44 4755.32,4478.13 4755.32,4457.25 ; 4765.32,4447.25 4764.56,4448 4755.32,4457.25 ; 4796.75,4447.25 4826.3,4447.25 C24.1@4835,4438.54
  Top Layer w10: C26.1@4150,3146.54 4183.37,3146.54 4202.01,3127.89 MIC2.2@4212.01,3127.89
  Top Layer w15: v1(3882,3584) 3888,3590 3888,3630 3878,3640 3878,3662 3880,3662 3888,3670 3888,3972 3930,4014 4066,4014 v1(4072,4020) ; 3986,3468 v1(3986,3480) ; MIC1.5@4174,3996 v1(4206,4028) ; C25.1@4185,4101.54 4194,4106 v1(4206,4118) ; v1@4248,3160 4248.3,3160.3 4262,3174 4262,3192 ; v1(4256,3990) 4256,3976 U7.1@4260.31,3966.55
  Top Layer w16: 4060,3146.5 C26.1@4150,3146.54 ; C22.1@4145,4201.54 C22.1@4146.5,4201.5 ; C22.1@4146,4202 C22.1@4146.5,4201.5 ; C22.1@4148,4200 C22.1@4146.5,4201.5 ; C26.1@4152,3154 v1(4152,3170) ; v1(4174,4226) 4210,4226 4234,4202 ; 4235,4201.5 C28.1@4200,4201.54 C22.1@4146.5,4201.5 ; v1(4710,4468) 4714,4464 4714,4442 4734,4442 4740,4448 4746.07,4448 4764.56,4448 4796,4448 4796.75,4447.25 4798,4446 ; 4800,4438.5 C24.1@4835,4438.54
  Inner2 w15: v1(4072,4020) 4088,4004 4102,3990 v1(4256,3990)
  Inner2 w16: v1(4152,3170) 4172,3190 4172,3694 4084,3782 4084,3876 4088,3880 4088,4004 4088,4120 v1(4168,4200) ; v1(4174,4226) 4206,4258 4206,4428 4228,4450 4312,4450 4426,4564 v1(4694,4564)
  Bottom Layer w9.84: v1(4242,3127.9) 4242,3160.3 v1(4248,3160.3)
  Bottom Layer w9.92: 4500.29,4431.56 v1(4620.29,4431.56)
  Bottom Layer w15: v1(3882,3584) v1(3986,3480) ; v1(4206,4028) v1(4206,4118)
  Bottom Layer w16: v1(4694,4564) 4700,4570 4752,4570 4766,4584 4794,4584 4806,4572 4806,4560 4842,4524 4802,4484 4800,4486 4782,4468 v1(4710,4468)
+3V3: C8.1 C9.1 C11.1 C12.1 C18.1 C20.1 C27.1 C29.1 C30.1 C31.1 D7.1 J5.1 J5.2 J6.1 J8.1 LED1.4 R3.2 R5.2 R6.2 R11.2 R12.2 R13.2 R14.2 R15.2 R21.1 U2.2 U4.6 U6.1 U6.3 U7.6 U8.6 U9.8 | length 10477.6
  Top Layer w5: C29.1@4260,4070 4260,4092 ; 4260,4113.4 4260,4092 ; C29.1@4260.3,4070 C29.1@4260.3,4072.69 ; 4302,4132 4314,4132 4314,4222 4328,4222 4343.4,4237.4 U6.3@4344,4238 ; 4304,3876 4330,3876 4330,3996 4346,4012 4346,4086 4300,4132 4260,4092
  Top Layer w10: 3800,3286.1 v1(3800,3306) U4.6@3799.98,3376.13 ; v1(4126,3642) 4126,3696 4256,3826 4298,3826 4308,3816 ; v1(4234.39,4094.43) 4260.3,4072.69 C29.1@4263.46,4070 ; LED1.4@4301.02,3746.66 v1(4319,3746.7) ; 4307.5,3815.6 v1@4310.58,3807.14 ; v1(4418,3400) 4458,3400 4476,3418 4476,3456 4492,3472 4492,3528 4506,3542 4500,3548 4500,3608 4480,3608 v1(4472,3600) ; v1@4584,4120 v1(4600,4120) ; v1@4720,4178 4720.18,4178.18 4720.44,4178.44 4728,4186 v1(4728,4202) ; v1(5826.11,4144.66) C31.1@5843.46,4140 ; D7.1@5933.84,4160 v1(5944.12,4174.74)
  Top Layer w12: v1(4257.17,4041.13) U7.6@4260.31,4023.45 v1(4260.3,4067.4) ; v1(4708.5,4525) 4704,4536 4735.3,4567.3 ; U8.6@4735.31,4478.44 4735.3,4525 4735.3,4526 4735.3,4567.3 ; 4735.3,4568.4 4735.3,4567.3 ; 4736,4568 4735.3,4567.3
  Top Layer w15: 3460.5,3395.5 R21.1@3550.46,3395.5 ; R21.1@3550,3396 3558,3404 3558,3546 3608,3546 v1(3616,3538) ; C18.1@3640.96,3390.5 3641,3480.5 ; 3642,3480 v1(3658,3496) ; v1(4126,3700) 4298,3872 4314,3872 v1(4320,3866) ; v1(4260.3,4067.4) C29.1@4263.46,4070 ; v1@4310.58,3807.14 v1(4313.66,3798.69) ; U6.3@4343.31,4237.4 4343.4,4237.4 v1(4367.3,4237.4) ; 4346,4086 R6.2@4362.96,4090 ; R14.2@4747.96,4130 4728.51,4163.75 ; v4(4752.6,4218.76) v1(4748,4175) ; 4848,4708 4872,4684 4872,4666 4864,4658 4864,4606 4855.62,4597.62 ; v4(4855.62,4677.73) 4855.62,4597.62 ; v4(4856.49,4184.42) C11.1@4870.63,4165 v1(4884.71,4184.42) ; v1(4994,3470) 5014,3450 5014,3384 5106,3384 5114,3376 C9.1@5123.46,3375 ; C8.1@5336,3490 5406,3560 v1(5408,3560) ; J6.1@6645.67,4986.94 v1(6669.7,4986.9) ; 4728.51,4163.75 v1(4748,4175) ; 4728.51,4163.75 4720.18,4178.18 v1(4720,4178.5) 4720.44,4178.44 v1(4748,4175) ; 4855.62,4597.62 4855.62,4576 v1(4834,4576) 4855.62,4597.62
  Top Layer w16: 4386.6,4900.1 J5.1@4427.42,4900.07 ; 4427.4,4810.1 J5.1@4427.42,4900.07 ; 4428,4810 4498,4740 ; J5.2@4476,4900 4498,4878 4498,4740 ; J5.2@4476.63,4900.07 J5.1@4427.42,4900.07 ; v1(4534,4704) 4498,4740 ; v1(4564,4712) 4556,4704 4546,4714 4534,4702 4522,4714 4510,4702 4498,4714 4498,4740 ; 4648.5,4525 v1(4708.5,4525) ; v1(4728,4694) 4748,4714 U9.8@4752,4710 ; C30.1@4738,4526 4735.3,4526 4720,4526 v1(4708.5,4525) ; C30.1@4738.46,4525 4735.3,4525 v1(4708.5,4525) ; U9.8@4757.6,4708.03 4847.6,4708
  Top Layer w20: R3.2@3335,3597.96 v1(3365,3598) ; v1(4014.3,4364.1) 4044.3,4364.1 ; v1(4028,3835) 4058,3835 ; 4148.5,3830 v1(4148.5,3860) ; C20.1@4200.63,3535 v1(4230.6,3535) ; v1(4233.5,4070) 4260,4070 4260.3,4070 C29.1@4263.46,4070 ; C27.1@4338.46,4295 v1(4308.5,4295) U6.3@4343.31,4237.4 ; U6.1@4343.31,4162.6 4363,4120 R6.2@4362.96,4090 ; R12.2@4545,4122.96 v1(4575,4123) ; R14.2@4747.96,4130 v1(4748,4175) ; C11.1@4870.63,4165 v1(4900.6,4165) C12.1@4878.46,4090 ; R15.2@4972.96,4090 v1(4973,4120) ; v1(5038,4090) R11.2@5067.96,4090 ; U2.2@5059.49,3374.8 v1(5093.5,3375) C9.1@5123.46,3375 ; R13.2@5130,3932.96 v1(5160,3933) ; R5.2@5162.04,3310 v1(5162,3340) ; C8.1@5335.63,3490 5335.6,3520 ; 5855.6,4041.2 v1(5885.6,4041.2) ; D7.1@5933.84,4160 v1(5963.8,4160)
  Inner1 w10: v1(4748,4175) v4(4856.49,4184.42)
  Inner2 w10: v1(4126,3404) 4118,3412 4118,3634 v1(4126,3642) ; v1@4318,3860 4314,3856 4364,3806 4410,3806 4418,3806 4422,3802 4426,3806 4436,3806 4442,3812 v1(4450,3804) ; v1(4872,3904) v1(4872,3944)
  Inner2 w15: v1(3616,3538) 3796,3718 3806,3718 ; v1(3658,3496) 3806,3644 3806,3718 ; v1(4144,3682) v1(4126,3700) 4108,3718 3806,3718 ; v1(4320,3866) 4350,3866 4410,3806 4420,3796 4444,3796 4446,3794 4864,3794 v1(4872,3786) ; v1(4834,4576) 4942,4468 4942,4124 ; v1(4872,3904) 4980,4012 4980,4116 4950,4116 4942,4124 ; v1(4900.6,4165) 4942,4124 ; v1(4994,3470) 5096,3572 5396,3572 v1(5408,3560) ; 5106,3366 5142,3366 5140,3368
  Bottom Layer w10: v1(3800,3306) 3810,3316 4244,3316 ; v1(4126,3404) 4134,3412 4148,3412 4244,3316 ; v1(4418,3400) v1@4416,3398 ; v1(4450,3804) 4440,3794 4440,3632 v1(4472,3600) ; v1(4600,4120) 4600,4090 4608.58,4081.42 4622,4068 4674,4068 4728,4122 v1(4728,4202) ; 4862,3398 4878,3414 4878,3441.9 4878,3466 4890,3478 v1(4890,3488) ; v1@4878.7,3951.3 v1(4889.02,3966.04) ; 4244,3316 4334,3316 ; 4334,3316 4376,3358 ; 4334,3316 4376,3316 4376,3358 ; 4376,3358 v1@4416,3398 ; 4376,3358 4376,3408 4400,3408 4410,3398 v1@4416,3398
  Bottom Layer w15: 4599,4072.8 4608.58,4081.42 v1(4616.84,4088.86)
  Bottom Layer w16: v1(4534,4704) 4718,4704 v1(4728,4694) ; v1(4564,4712) v1(4812,4712) ; J8.1@4839.95,3441.93 4878,3441.9 4930,3441.9 ; J8.1@4840,3442 4874,3442
  Bottom Layer w20: 3370.8,4073.1 v1(3400.8,4073.1) ; v1@4878.7,3951.3 4878.7,3981.3
BTN_BACK: SW2.1 U2.38 | length 1384.3
  Top Layer w10: v1@3858.9,3848 SW2.1@3858.86,4087.4 3858.9,4177.4 ; v1(4328,3426) U2.38@4366,3426 ; U2.38@4370.51,3424.8 4460.5,3424.8
  Bottom Layer w10: v1(3858,3848) 3858,3710 3808,3660 3808,3638 3830,3616 4234,3616 4256,3594 4256,3528 4254,3526 4254,3448 4276,3426 v1(4328,3426)
BTN_OK: SW1.1 U2.39 | length 688
  Top Layer w10: 3858,3376 3858.9,3376 ; 3858.9,3375.4 3858.9,3376 ; SW1.1@3858.86,3465.35 3858.9,3376 ; v1(4278,3376) 3858.9,3376 ; v1(4328,3376) U2.39@4366,3376 ; U2.39@4370.51,3374.8 4460.5,3374.8
  Bottom Layer w10: v1(4278,3376) v1(4328,3376)
BTN_REC: SW3.1 U2.15 | length 2811.5
  Top Layer w10: SW3.1@3858,4698 3992,4564 4452,4564 4724,4836 5116,4836 5138,4814 5138,4554 5298,4394 5298,4064 5266,4032 5184,4114 v1(5184,4116) ; SW3.1@3858.86,4697.64 3858.9,4787.6 ; U2.15@4990,4025.2 4990,4060.2 ; U2.15@4994,4046 v1(5022,4046)
  Inner2 w10: v1(5022,4046) 5044,4046 5066,4068 5066,4112 5148,4112 5154,4106 5174,4106 v1(5184,4116)
C18_N3: L1.1 U4.9 | length 1178.7
  Top Layer w10: 3612,3076 3610,3074 3396,3074 3396,3256 3442,3302 3442,3456 3550,3564 3662,3564 3766,3460 3766,3436 ; 3614.6,3080 L1.1@3614.64,3170 ; 3765,3435.2 U4.9@3799.98,3435.18
C18_N4: L1.2 U4.7 | length 578.5
  Top Layer w12: L1.2@3445.36,3170 3445.4,3260 ; 3448,3264 3450,3266 3656,3266 3660,3262 3760,3262 3760,3396 U4.7@3800,3396
C18_N6: R20.1 R21.2 U4.4 | length 610.3
  Top Layer w12: 3584,3306 3584.5,3305.5 ; R21.2@3584.54,3395.5 3584.5,3305.5 ; v1(3646,3292) 3598,3292 3584.5,3305.5 ; v1(3734,3288) 3710,3312 3710,3396 U4.4@3734,3396 ; R20.1@3758,3206 v1(3758,3224) ; R20.1@3759.54,3200.5 3804.5,3200.5
  Inner2 w12: v1(3646,3292) 3676,3262 3728,3262 v1(3784,3206)
  Bottom Layer w12: v1(3734,3288) 3758,3264 v1(3758,3224)
CC1: J2.A5 R7.1 | length 976.6
  Top Layer w10: R7.1@3780,4482.96 3870,4483
  Bottom Layer w10: J2.A5@3321.8,4034.3 3411.8,4034.3 ; 3412,4034 3414,4032 3698,4032 3780,4114 3780,4344 3852,4416 v1(3852,4478)
CC2: J2.B5 R8.1 | length 771.3
  Top Layer w10: v1@3513,4658 R8.1@3602.96,4658
  Bottom Layer w10: J2.B5@3321.8,4152.4 3411.8,4152.4 ; 3412,4152 3440,4180 3498,4180 3498,4286 3484,4300 3484,4634 v1(3508,4658)
CHG_PGOOD: R3.1 U1.7 | length 994.3
  Top Layer w6: R3.1@3335,3632.04 3344,3622 3388,3622 3388,3578 3656,3578 3706,3628 3856,3628 3856,3660 3834,3682 3824,3672 3566,3672 3530,3708 U1.7@3530,3726
EN: C10.1 J8.5 R5.1 SW5.1 U2.3 | length 3119.4
  Top Layer w10: v1(3972,3746) 4006,3712 4068,3712 4068,3496 4192,3496 v1(4200,3488) ; U2.3@5033.5,3435 U2.3@5034,3435 ; U2.3@5059.49,3424.8 U2.3@5060,3424.8 ; U2.3@5060,3424 U2.3@5060,3424.8 ; U2.3@5060,3430 U2.3@5060,3424.8 ; v1(5110,3478) 5110,3460 U2.3@5085,3435 ; C10.1@5118,3428 5124,3434 v1(5124,3406) ; C10.1@5119.5,3424.8 U2.3@5060,3424.8 ; C10.1@5123.46,3435 U2.3@5085,3435 ; R5.1@5124,3312 v1(5124,3334) ; 5128,3250 R5.1@5127.96,3310 ; U2.3@5034,3435 5084,3434 U2.3@5085,3435 ; U2.3@5034,3435 U2.3@5085,3435
  Inner2 w10: v1(3082,3712) 3082,3690 3256,3690 3264,3698 3438,3698 3452,3712 3554,3712 3554,3680 3564,3670 3608,3670 3632,3694 3696,3694 3738,3736 3962,3736 v1(3972,3746) ; v1(4200,3488) 4222,3510 4318,3510 4322,3514 4422,3514 4428,3520 4484,3520 4512,3548 4766,3548 4870,3444 5006,3444 5034,3472 5054,3472 5060,3478 v1(5110,3478) ; v1(4644,3490) 4644,3544
  Bottom Layer w10: SW5.1@3048,3712 v1(3082,3712) ; 4643.1,3351.9 J8.5@4643.1,3441.93 ; J8.5@4644,3442 v1(4644,3490) ; v1(5124,3334) v1(5124,3406)
FG_CTG: C21.1 U5.1 | length 178.6
  Top Layer w10: 3630.5,3723.1 U5.1@3630.47,3758.09 ; 3634,3736 3652,3718 3652,3704 C21.1@3662,3694 ; C21.1@3661.54,3695 3751.5,3695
